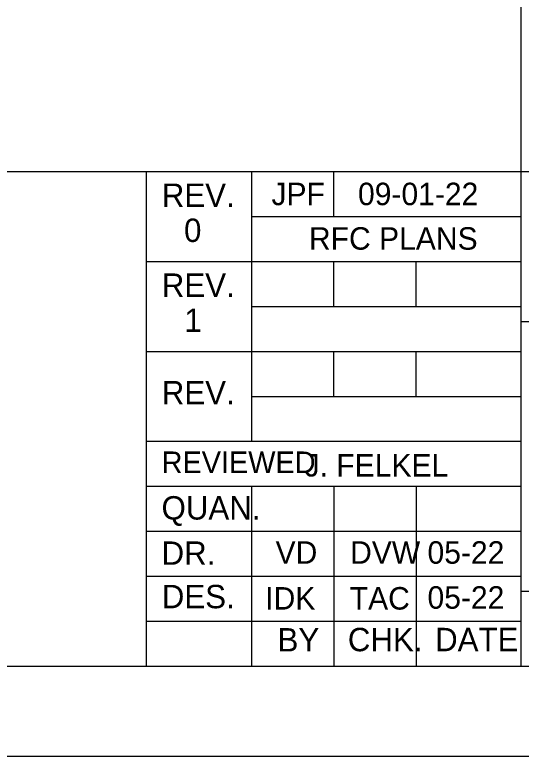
# Model space of a CAD drawing. Extents: x 1970675.2 to 1970711.3, y 796145.2 to 796167.2.
# Drawn here: x 1970702.503 to 1970705.319, y 796145.246 to 796149.367 of the extents above; entities that cross this region are included whole.
import ezdxf

# ---------------------------------------------------------------- set-up
doc = ezdxf.new("R2010")
doc.units = 0
for name, color, linetype in [('BR_BORDER LINES', 7, 'Continuous'), ('BR_TEXT', 7, 'Continuous'), ('Level 31', 7, 'Continuous')]:
    doc.layers.add(name, color=color, linetype=linetype)

msp = doc.modelspace()

# ---------------------------------------------------------------- linework, layer by layer
at = {"layer": 'BR_BORDER LINES'}
for p, q in [((1970705.3189, 796145.7463), (1970705.3189, 796151.0229)), ((1970697.8703, 796148.4964), (1970703.2355, 796148.4964)), ((1970703.2355, 796145.7463), (1970703.2355, 796148.4964)), ((1970703.2355, 796148.4964), (1970710.7358, 796148.4964)), ((1970703.8189, 796148.4964), (1970703.8189, 796146.9963)), ((1970704.2772, 796148.2464), (1970704.2772, 796148.4964)), ((1970703.8189, 796148.2464), (1970705.3189, 796148.2464)), ((1970703.2355, 796147.9964), (1970705.3189, 796147.9964)), ((1970704.2772, 796147.7464), (1970704.2772, 796147.9964)), ((1970704.7356, 796147.7464), (1970704.7356, 796147.9964)), ((1970703.8189, 796147.7464), (1970705.3189, 796147.7464)), ((1970705.3189, 796147.663), (1970705.3189, 796147.663)), ((1970705.3189, 796147.663), (1970710.736, 796147.663)), ((1970703.2355, 796147.4964), (1970705.3189, 796147.4964)), ((1970704.2772, 796147.2463), (1970704.2772, 796147.4964)), ((1970704.7356, 796147.2463), (1970704.7356, 796147.4964)), ((1970703.8189, 796147.2463), (1970705.3189, 796147.2463)), ((1970703.2355, 796146.9963), (1970705.3189, 796146.9963)), ((1970703.2355, 796146.7463), (1970705.3189, 796146.7463)), ((1970703.8189, 796146.7463), (1970703.8189, 796145.7463)), ((1970704.2772, 796146.7463), (1970704.2772, 796145.7463)), ((1970704.7356, 796146.7463), (1970704.7356, 796145.7463)), ((1970703.2355, 796146.4963), (1970705.3189, 796146.4963)), ((1970703.2355, 796146.2463), (1970705.3189, 796146.2463)), ((1970705.3189, 796146.163), (1970710.7358, 796146.163)), ((1970703.2355, 796145.9963), (1970705.3189, 796145.9963)), ((1970677.0698, 796145.7463), (1970710.7358, 796145.7463))]:
    msp.add_line(p, q, dxfattribs=at)
at = {"layer": 'Level 31'}
msp.add_lwpolyline([(1970675.2365, 796145.2464), (1970711.2364, 796145.2464), (1970711.2364, 796167.2463), (1970675.2365, 796167.2463)], close=True, dxfattribs=at)

# ---------------------------------------------------------------- texts
at = {"layer": 'BR_TEXT'}
for s, height, p in [('REV.', 0.13001, (1970703.3202, 796148.2993)), ('JPF', 0.12499, (1970703.9304, 796148.3088)), ('09-01-22', 0.12499, (1970704.4116, 796148.3088)), ('0', 0.13, (1970703.4441, 796148.1043)), ('RFC PLANS', 0.12499, (1970704.1388, 796148.0613)), ('REV.', 0.13001, (1970703.3202, 796147.7993)), ('1', 0.13, (1970703.4461, 796147.6043)), ('REV.', 0.13001, (1970703.3202, 796147.2018)), ('REVIEWED', 0.12, (1970703.3195, 796146.8198)), ('J. FELKEL', 0.12499, (1970704.1145, 796146.8007)), ('QUAN.', 0.13001, (1970703.3189, 796146.5615)), ('DR.', 0.13001, (1970703.3191, 796146.31)), ('VD', 0.12499, (1970703.9531, 796146.316)), ('DVW', 0.12499, (1970704.3677, 796146.316)), ('05-22', 0.12499, (1970704.798, 796146.316)), ('DES.', 0.13001, (1970703.3202, 796146.0686)), ('IDK', 0.12499, (1970703.8957, 796146.0612)), ('TAC', 0.12499, (1970704.3656, 796146.0612)), ('05-22', 0.12499, (1970704.798, 796146.066)), ('BY', 0.13001, (1970703.9642, 796145.8283)), ('CHK.', 0.13001, (1970704.355, 796145.8296)), ('DATE', 0.13001, (1970704.8402, 796145.8297))]:
    msp.add_text(s, height=height, dxfattribs=at).set_placement(p)

doc.saveas('drawing.dxf')
